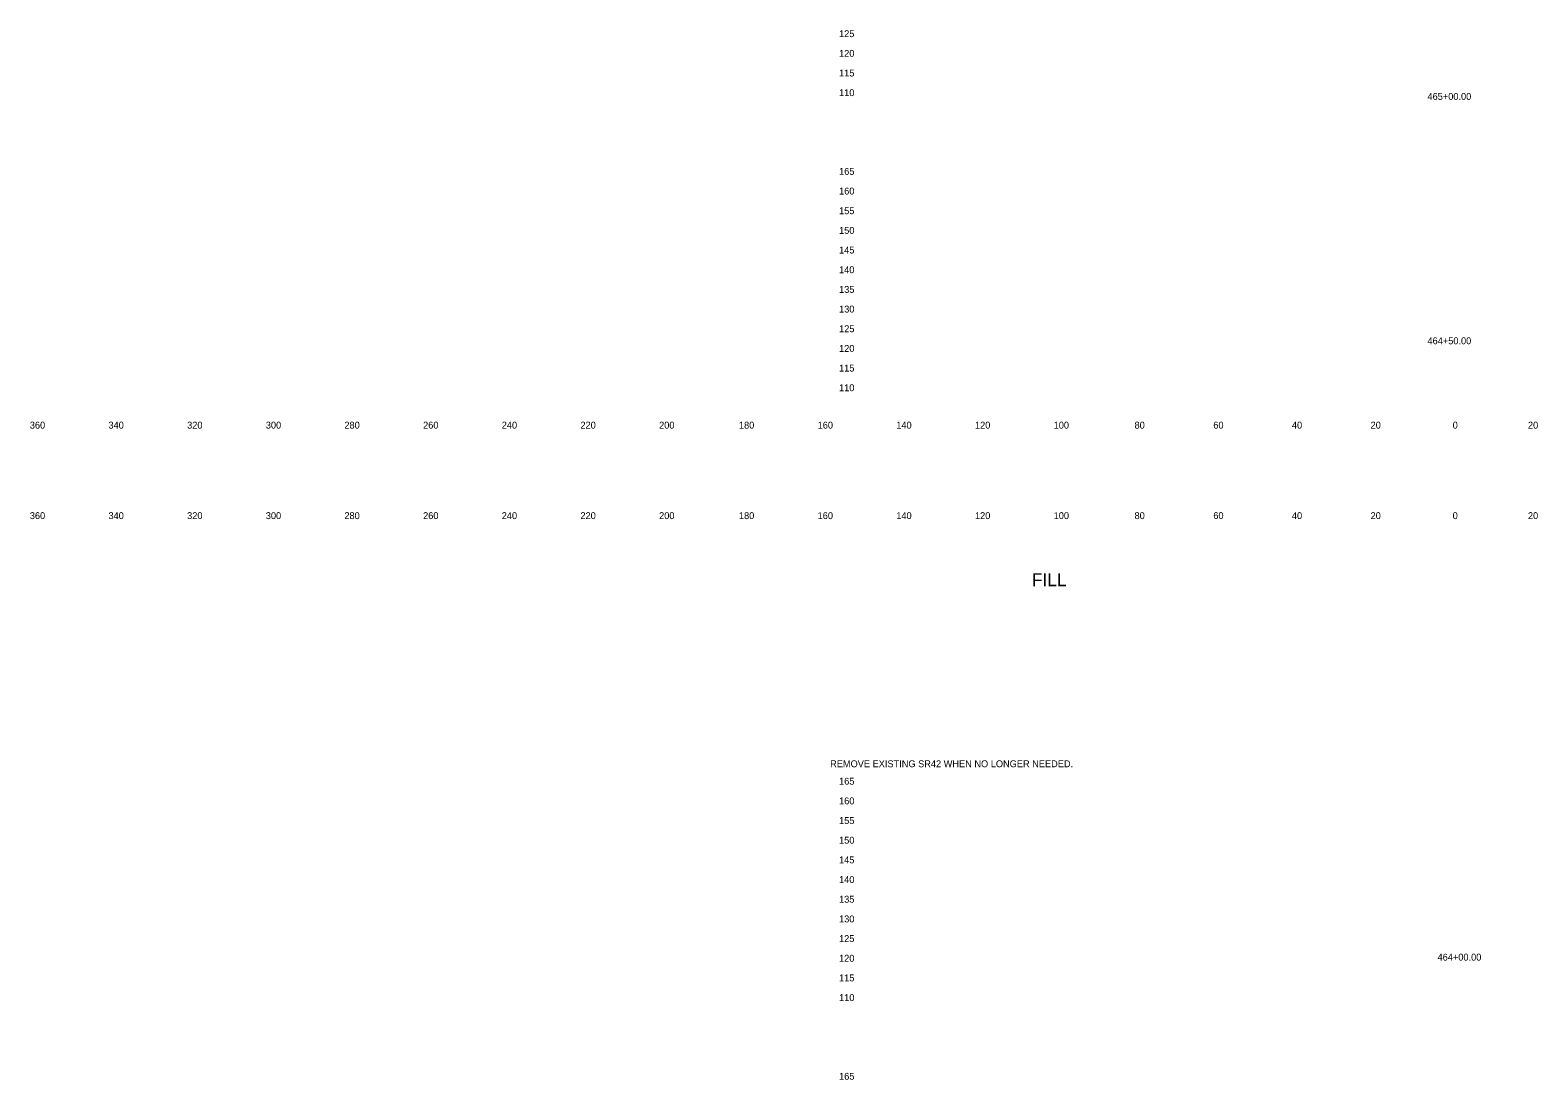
# Model space of a CAD drawing. Extents: x 21281 to 22024, y 6472 to 15208.
# Drawn here: x 21280.5 to 21663.8, y 8379.8 to 8646.6 of the extents above; entities that cross this region are included whole.
import ezdxf

# ---------------------------------------------------------------- set-up
doc = ezdxf.new("R2010")
doc.units = 0
for name, color, linetype in [('XS_SHEET_LABELS_ELEVATION', 7, 'Continuous'), ('XS_SHEET_LABELS_OFFSET', 7, 'Continuous'), ('XS_SHEET_LABELS_STATION', 7, 'Continuous')]:
    doc.layers.add(name, color=color, linetype=linetype)

msp = doc.modelspace()

# ---------------------------------------------------------------- texts
at = {"layer": 'XS_SHEET_LABELS_ELEVATION'}
for s, p in [('  125  ', (21484.84, 8644.84)), ('  120  ', (21484.84, 8639.84)), ('  115  ', (21484.84, 8634.84)), ('  110  ', (21484.84, 8629.84)), ('  165  ', (21484.84, 8609.84)), ('  160  ', (21484.84, 8604.84)), ('  155  ', (21484.84, 8599.84)), ('  150  ', (21484.84, 8594.84)), ('  145  ', (21484.84, 8589.84)), ('  140  ', (21484.84, 8584.84)), ('  135  ', (21484.84, 8579.84)), ('  130  ', (21484.84, 8574.84)), ('  125  ', (21484.84, 8569.84)), ('  120  ', (21484.84, 8564.84)), ('  115  ', (21484.84, 8559.84)), ('  110  ', (21484.84, 8554.84)), ('  165  ', (21484.84, 8454.84)), ('  160  ', (21484.84, 8449.84)), ('  155  ', (21484.84, 8444.84)), ('  150  ', (21484.84, 8439.84)), ('  145  ', (21484.84, 8434.84)), ('  140  ', (21484.84, 8429.84)), ('  135  ', (21484.84, 8424.84)), ('  130  ', (21484.84, 8419.84)), ('  125  ', (21484.84, 8414.84)), ('  120  ', (21484.84, 8409.84)), ('  115  ', (21484.84, 8404.84)), ('  110  ', (21484.84, 8399.84)), ('  165  ', (21484.84, 8379.84))]:
    msp.add_text(s, height=1.75, dxfattribs=at).set_placement(p)
at = {"layer": 'XS_SHEET_LABELS_OFFSET'}
for s, height, p in [('  360  ', 1.75, (21279.14, 8545.34)), ('  340  ', 1.75, (21299.13, 8545.34)), ('  320  ', 1.75, (21319.13, 8545.34)), ('  300  ', 1.75, (21339.13, 8545.34)), ('  280  ', 1.75, (21359.1, 8545.34)), ('  260  ', 1.75, (21379.11, 8545.34)), ('  240  ', 1.75, (21399.1, 8545.34)), ('  220  ', 1.75, (21419.1, 8545.34)), ('  200  ', 1.75, (21439.1, 8545.34)), ('  180  ', 1.75, (21459.39, 8545.34)), ('  160  ', 1.75, (21479.4, 8545.34)), ('  140  ', 1.75, (21499.39, 8545.34)), ('  120  ', 1.75, (21519.39, 8545.34)), ('  100  ', 1.75, (21539.39, 8545.34)), ('  80  ', 1.75, (21559.95, 8545.34)), ('  60  ', 1.75, (21579.97, 8545.34)), ('  40  ', 1.75, (21599.95, 8545.34)), ('  20  ', 1.75, (21619.95, 8545.34)), ('  0  ', 1.75, (21640.81, 8545.34)), ('  0  ', 1.75, (21640.81, 8545.34)), ('  20  ', 1.75, (21659.95, 8545.34)), ('  360  ', 1.75, (21279.14, 8522.34)), ('  340  ', 1.75, (21299.13, 8522.34)), ('  320  ', 1.75, (21319.13, 8522.34)), ('  300  ', 1.75, (21339.13, 8522.34)), ('  280  ', 1.75, (21359.1, 8522.34)), ('  260  ', 1.75, (21379.11, 8522.34)), ('  240  ', 1.75, (21399.1, 8522.34)), ('  220  ', 1.75, (21419.1, 8522.34)), ('  200  ', 1.75, (21439.1, 8522.34)), ('  180  ', 1.75, (21459.39, 8522.34)), ('  160  ', 1.75, (21479.4, 8522.34)), ('  140  ', 1.75, (21499.39, 8522.34)), ('  120  ', 1.75, (21519.39, 8522.34)), ('  100  ', 1.75, (21539.39, 8522.34)), ('  80  ', 1.75, (21559.95, 8522.34)), ('  60  ', 1.75, (21579.97, 8522.34)), ('  40  ', 1.75, (21599.95, 8522.34)), ('  20  ', 1.75, (21619.95, 8522.34)), ('  0  ', 1.75, (21640.81, 8522.34)), ('  0  ', 1.75, (21640.81, 8522.34)), ('  20  ', 1.75, (21659.95, 8522.34)), ('FILL', 3.273, (21535.18, 8505.29))]:
    msp.add_text(s, height=height, dxfattribs=at).set_placement(p)
at = {"layer": 'XS_SHEET_LABELS_STATION'}
for s, p in [('  465+00.00  ', (21634.41, 8628.89)), ('  464+50.00  ', (21634.41, 8566.78)), ('REMOVE EXISTING SR42 WHEN NO LONGER NEEDED.', (21483.87, 8459.27)), ('  464+00.00  ', (21636.97, 8410.12))]:
    msp.add_text(s, height=1.75, dxfattribs=at).set_placement(p)

doc.saveas('drawing.dxf')
